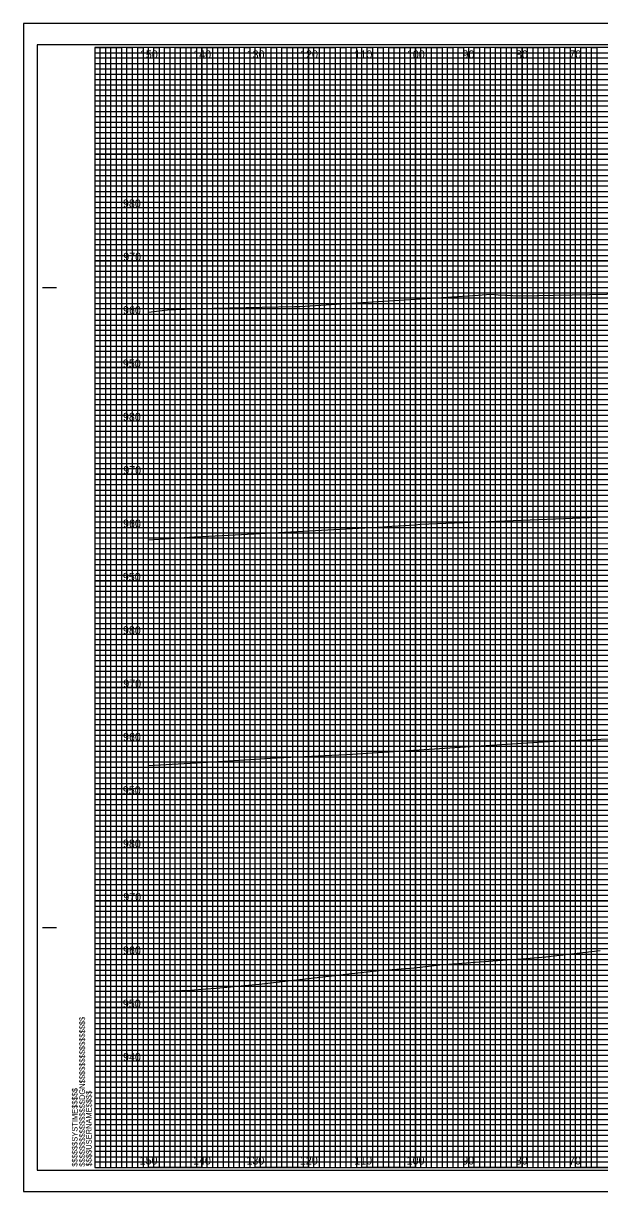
# Model space of a CAD drawing. Extents: x -13 to 760, y -5 to 1491.
# Drawn here: x -13.4 to 94.5, y 952.5 to 1171.5 of the extents above; entities that cross this region are included whole.
import ezdxf

# ---------------------------------------------------------------- set-up
doc = ezdxf.new("R2010")
doc.units = 0
for name, color, linetype in [('Default', 7, 'Continuous'), ('Exist XS Ground Line', 7, 'Continuous'), ('Prop XS Elevation Labels', 7, 'Continuous'), ('Prop XS Offset Labels', 7, 'Continuous'), ('Sheet Cross Section CELL', 7, 'Continuous'), ('Sheet Cross Section Grid Major CELL', 7, 'Continuous'), ('Sheet Cross Section Grid Middle CELL', 7, 'Continuous'), ('Sheet Cross Section Grid Minor 1 CELL', 7, 'Continuous'), ('Sheet Cross Section Grid Minor 2 CELL', 7, 'Continuous'), ('Sheet Cutting Line CELL', 7, 'Continuous'), ('Sheet DOT Grid CELL', 7, 'Continuous'), ('Sheet Plot Border Inside CELL', 7, 'Continuous'), ('Sheet Plot Border Outside CELL', 7, 'Continuous')]:
    doc.layers.add(name, color=color, linetype=linetype)

msp = doc.modelspace()

# ---------------------------------------------------------------- linework, layer by layer
at = {"layer": 'Exist XS Ground Line'}
for points in [[(10, 1117.39), (13.59, 1117.79), (16.76, 1117.93), (17.9, 1117.98), (19.18, 1118.04), (37.38, 1118.41), (38.34, 1118.46), (71.78, 1120.56), (74.07, 1120.73), (75.48, 1120.63), (79.56, 1120.43), (105.65, 1120.95)], [(10, 1117.39), (13.59, 1117.79), (16.76, 1117.93), (17.9, 1117.98), (19.18, 1118.04), (37.38, 1118.41), (38.34, 1118.46), (71.78, 1120.56), (74.07, 1120.73), (75.48, 1120.63), (79.56, 1120.43), (105.65, 1120.95)], [(10, 1074.69), (18.61, 1075.26), (25.12, 1075.57), (53.98, 1077.14), (55.61, 1077.26), (56.75, 1077.3), (59.91, 1077.53), (60.98, 1077.61), (102.01, 1079.28)], [(10, 1074.69), (18.61, 1075.26), (25.12, 1075.57), (53.98, 1077.14), (55.61, 1077.26), (56.75, 1077.3), (59.91, 1077.53), (60.98, 1077.61), (102.01, 1079.28)], [(10, 1032.38), (21.11, 1033.01), (32.79, 1033.79), (48.2, 1034.55), (67.4, 1035.78), (68.4, 1035.84), (84.99, 1036.87), (110.02, 1038.03)], [(10, 1032.38), (21.11, 1033.01), (32.79, 1033.79), (48.2, 1034.55), (67.4, 1035.78), (68.4, 1035.84), (84.99, 1036.87), (110.02, 1038.03)], [(10, 989.95), (12.76, 990.08), (17.94, 990.31), (20.77, 990.55), (22.71, 990.66), (30.73, 991.39), (48.12, 993.41), (52.64, 993.88), (53.2, 993.95), (59.79, 994.48), (64.6, 995), (67.1, 995.23), (74.49, 995.75), (80.75, 996.22), (84.4, 996.53), (85.41, 996.64), (94.63, 997.69)], [(10, 989.95), (12.76, 990.08), (17.94, 990.31), (20.77, 990.55), (22.71, 990.66), (30.73, 991.39), (48.12, 993.41), (52.64, 993.88), (53.2, 993.95), (59.79, 994.48), (64.6, 995), (67.1, 995.23), (74.49, 995.75), (80.75, 996.22), (84.4, 996.53), (85.41, 996.64), (94.63, 997.69)]]:
    msp.add_lwpolyline(points, dxfattribs=at)
at = {"layer": 'Sheet Cross Section CELL'}
for p, q in [((-9.8, 1122.01), (-7.3, 1122.01)), ((-9.7, 1122.01), (-7.2, 1122.01)), ((-9.8, 1002.01), (-7.3, 1002.01)), ((-9.7, 1002.01), (-7.2, 1002.01)), ((0, 957.01), (0, 957.01)), ((0, 957.01), (0, 957.01)), ((0, 957.01), (0, 957.01)), ((0, 957.01), (0, 957.01)), ((0, 957.01), (0, 957.01)), ((0, 957.01), (0, 957.01)), ((0, 957.01), (0, 957.01))]:
    msp.add_line(p, q, dxfattribs=at)
msp.add_lwpolyline([(320, 1167.01), (0, 1167.01), (0, 957.01), (320, 957.01)], close=True, dxfattribs=at)
at = {"layer": 'Sheet Cross Section Grid Major CELL'}
for p, q in [((10, 1167.01), (0, 1167.01)), ((10, 957.01), (10, 1167.01)), ((30, 1167.01), (20, 1167.01)), ((20, 1167.01), (20, 957.01)), ((30, 957.01), (30, 1167.01)), ((50, 1167.01), (40, 1167.01)), ((40, 1167.01), (40, 957.01)), ((50, 957.01), (50, 1167.01)), ((70, 1167.01), (60, 1167.01)), ((60, 1167.01), (60, 957.01)), ((70, 957.01), (70, 1167.01)), ((90, 1167.01), (80, 1167.01)), ((80, 1167.01), (80, 957.01)), ((90, 957.01), (90, 1167.01)), ((20, 957.01), (10, 957.01)), ((40, 957.01), (30, 957.01)), ((60, 957.01), (50, 957.01)), ((80, 957.01), (70, 957.01)), ((100, 957.01), (90, 957.01))]:
    msp.add_line(p, q, dxfattribs=at)
for points in [[(0, 1157.01), (320, 1157.01), (320, 1147.01), (0, 1147.01)], [(0, 1137.01), (320, 1137.01), (320, 1127.01), (0, 1127.01)], [(0, 1117.01), (320, 1117.01), (320, 1107.01), (0, 1107.01)], [(0, 1097.01), (320, 1097.01), (320, 1087.01), (0, 1087.01)], [(0, 1077.01), (320, 1077.01), (320, 1067.01), (0, 1067.01)], [(0, 1057.01), (320, 1057.01), (320, 1047.01), (0, 1047.01)], [(0, 1037.01), (320, 1037.01), (320, 1027.01), (0, 1027.01)], [(0, 1017.01), (320, 1017.01), (320, 1007.01), (0, 1007.01)], [(0, 997.01), (320, 997.01), (320, 987.01), (0, 987.01)], [(0, 977.01), (320, 977.01), (320, 967.01), (0, 967.01)]]:
    msp.add_lwpolyline(points, dxfattribs=at)
at = {"layer": 'Sheet Cross Section Grid Middle CELL'}
for points in [[(0, 1167.01), (5, 1167.01), (5, 957.01), (15, 957.01), (15, 1167.01), (25, 1167.01), (25, 957.01), (35, 957.01), (35, 1167.01), (45, 1167.01), (45, 957.01), (55, 957.01), (55, 1167.01), (65, 1167.01), (65, 957.01), (75, 957.01), (75, 1167.01), (85, 1167.01), (85, 957.01), (95, 957.01)], [(0, 1162.01), (275, 1162.01)], [(0, 1142.01), (320, 1142.01), (320, 1152.01), (0, 1152.01)], [(0, 1122.01), (320, 1122.01), (320, 1132.01), (0, 1132.01)], [(0, 1102.01), (320, 1102.01), (320, 1112.01), (0, 1112.01)], [(0, 1082.01), (320, 1082.01), (320, 1092.01), (0, 1092.01)], [(0, 1062.01), (320, 1062.01), (320, 1072.01), (0, 1072.01)], [(0, 1042.01), (320, 1042.01), (320, 1052.01), (0, 1052.01)], [(0, 1022.01), (320, 1022.01), (320, 1032.01), (0, 1032.01)], [(0, 1002.01), (320, 1002.01), (320, 1012.01), (0, 1012.01)], [(0, 982.01), (320, 982.01), (320, 992.01), (0, 992.01)], [(0, 962.01), (320, 962.01), (320, 972.01), (0, 972.01)]]:
    msp.add_lwpolyline(points, dxfattribs=at)
at = {"layer": 'Sheet Cross Section Grid Minor 1 CELL'}
for p, q in [((0, 1166.01), (260, 1166.01)), ((260, 1164.99), (0, 1164.99)), ((0, 1164.99), (0, 1164.01)), ((0, 1164.01), (260, 1164.01)), ((260, 1162.9), (0, 1162.9)), ((0, 1162.9), (0, 1161.01)), ((0, 1161.01), (320, 1161.01))]:
    msp.add_line(p, q, dxfattribs=at)
for points in [[(0, 1160.01), (270, 1160.01), (320, 1160.01), (320, 1159.01), (0, 1159.01)], [(0, 1158.01), (320, 1158.01), (320, 1156.01), (0, 1156.01)], [(0, 1155.01), (320, 1155.01), (320, 1154.01), (0, 1153.99)], [(0, 1153.01), (320, 1153.01), (320, 1151.01), (0, 1151.01)], [(0, 1150.01), (320, 1150.01), (320, 1149.01), (0, 1149.01)], [(0, 1148.01), (320, 1148.01), (320, 1146.01), (0, 1146.01)], [(0, 1145.01), (320, 1145.01), (320, 1144.01), (0, 1144.01)], [(0, 1143.01), (320, 1143.01), (320, 1141.01), (0, 1141.01)], [(0, 1140.01), (320, 1140.01), (320, 1139.01), (0, 1139.01)], [(0, 1138.01), (320, 1138.01), (320, 1136.01), (0, 1136.01)], [(0, 1135.01), (320, 1135.01), (320, 1134.01), (0, 1134.01)], [(0, 1133.01), (320, 1133.01), (320, 1130.96), (320, 1130.01), (320, 1129.01), (0, 1129.01)], [(0, 1131.01), (320, 1131.01), (320, 1130.01), (0, 1130.01)], [(0, 1128.01), (320, 1128.01), (320, 1126.01), (0, 1126.04)], [(0, 1126.04), (320, 1126.01), (320, 1125.01), (0, 1125.01)], [(0, 1124.01), (320, 1124.01), (320, 1123.01), (0, 1123.01)], [(0, 1121.01), (320, 1121.01), (320, 1120.01), (0, 1120.01)], [(0, 1119.01), (320, 1119.01), (320, 1118.01), (0, 1118.01)], [(-0.07, 1115.9), (320, 1115.9), (320, 1114.89), (-0.07, 1114.89)], [(0, 1114.01), (320, 1114.01), (320, 1113.01), (0, 1113.01)], [(0, 1111.01), (320, 1111.01), (320, 1110.01), (0, 1110.01)], [(0, 1109.01), (320, 1109.01), (320, 1108.01), (0, 1108.01)], [(0, 1106.01), (320, 1106.01), (320, 1105.01), (0, 1105.01)], [(0, 1104.01), (320, 1104.01), (320, 1103.01), (0, 1103.01)], [(0, 1101.01), (320, 1101.01), (320, 1100.01), (0, 1100.01)], [(0, 1099.01), (320, 1099.01), (320, 1098.01), (0, 1098.01)], [(0, 1096.01), (320, 1096.01), (319.99, 1094.99), (0, 1095.01)], [(0, 1094.01), (320, 1094.01), (320, 1093.01), (0, 1093.01)], [(0, 1091.01), (320, 1091.01), (320, 1090.01), (0, 1090.01)], [(0, 1089.01), (320, 1089.01), (320, 1088.01), (0, 1088.01)], [(0, 1086.01), (320, 1086.01), (320, 1085.01), (0, 1085.01)], [(0, 1084.01), (320, 1084.01), (320, 1083.01), (0, 1083.01)], [(0, 1081.01), (320, 1081.01), (320, 1080.01), (0, 1080.01)], [(0, 1079.01), (320, 1079.01), (320, 1078.01), (0, 1078.01)], [(0, 1076.01), (320, 1076.01), (320, 1075.01), (0, 1075.01)], [(0, 1074), (320.07, 1073.92), (320, 1073.01), (0, 1073.01)], [(0, 1071.01), (320, 1071.01), (320, 1070.01), (0, 1070.01)], [(0, 1069.01), (320, 1069.01), (320, 1068.01), (0, 1068.01)], [(0, 1066.01), (320, 1066.01), (320, 1065.01), (0, 1065.01)], [(0, 1064.01), (320, 1064.01), (320, 1063.01), (0, 1063.01)], [(0, 1061.01), (320, 1061.01), (320, 1060.01), (0, 1060.01)], [(0, 1059.01), (320, 1059.01), (320, 1058.01), (0, 1058.01)], [(0, 1056.01), (320, 1056.01), (320, 1055.01), (0, 1055.01)], [(0, 1054.01), (320, 1054.01), (320, 1053.01), (0, 1053.01)], [(0, 1051.01), (320, 1051.01), (320, 1050.01), (0, 1050.01)], [(0, 1049.01), (320, 1049.01), (320, 1048.01), (0, 1048.01)], [(0, 1046.01), (320, 1046.01), (320, 1045.01), (0, 1045.01)], [(0, 1044.01), (320, 1044.01), (320, 1043.01), (0, 1043.01)], [(0, 1041.01), (320, 1041.01), (320, 1040.01), (0, 1040.01)], [(0, 1039.01), (320, 1039.01), (320, 1038.01), (0, 1038.01)], [(0, 1036.01), (320, 1036.01), (319.99, 1034.99), (0, 1035.01)], [(0, 1034.01), (320, 1034.01), (320, 1033.01), (0, 1033.01)], [(0, 1031.01), (320, 1031.01), (320, 1030.01), (0, 1030.01)], [(0, 1029.01), (320, 1029.01), (320, 1028.01), (0, 1028.01)], [(0, 1026.01), (320, 1026.01), (320, 1025.01), (0, 1025.01)], [(0, 1024.01), (320, 1024.01), (320, 1023.01), (0, 1023.01)], [(0, 1021.01), (320, 1021.01), (320, 1020.01), (0, 1020.01)], [(0, 1019.01), (320, 1019.01), (320, 1018.01), (0, 1018.01)], [(0, 1016.01), (320, 1016.01), (320, 1015.01), (0, 1015.01)], [(0, 1014), (320.07, 1013.92), (320, 1013.01), (0, 1013.01)], [(0, 1011.01), (320, 1011.01), (320, 1010.01), (0, 1010.01)], [(0, 1009.01), (320, 1009.01), (320, 1008.01), (0, 1008.01)], [(0, 1006.01), (320, 1006.01), (320, 1005.01), (0, 1005.01)], [(0, 1004.01), (320, 1004.01), (320, 1003.01), (0, 1003.01)], [(0, 1001.01), (320, 1001.01), (320, 1000.01), (0, 1000.01)], [(0, 999.01), (320, 999.01), (320, 998.01), (0, 998.01)], [(0, 996.01), (320, 996.01), (320, 995.01), (0, 995.01)], [(0, 994.01), (320, 994.01), (320, 993.01), (0, 993.01)], [(0, 991.01), (320, 991.01), (320, 990.01), (0, 990.01)], [(0, 989.01), (320, 989.01), (320, 988.01), (0, 988.01)], [(0, 986.01), (320, 986.01), (320, 985.01), (0, 985.01)], [(0, 984.01), (320, 984.01), (320, 983.01), (0, 983.01)], [(0, 981.01), (320, 981.01), (320, 980.01), (0, 980.01)], [(0, 979.01), (320, 979.01), (320, 978.01), (0, 978.01)], [(0, 976.01), (320, 976.01), (320, 975.01), (0, 975.01)], [(0, 974.01), (320, 974.01), (320, 973.01), (0, 973.01)], [(0, 971.01), (320, 971.01), (320, 970.01), (0, 970.01)], [(0, 969.01), (320, 969.01), (320, 968.01), (0, 968.01)], [(0, 966.01), (320, 966.01), (320, 965.01), (0, 965.01)], [(0, 964.01), (320, 964.01), (320, 963.01), (0, 963.01)], [(0, 961.01), (320, 961.01), (320, 960.01), (0, 960.01)], [(0, 959.01), (320, 959.01), (320, 958.01), (0, 958.01)]]:
    msp.add_lwpolyline(points, dxfattribs=at)
at = {"layer": 'Sheet Cross Section Grid Minor 2 CELL'}
for points in [[(0, 957.01), (1, 957.01), (1, 1167.01), (2, 1167.01), (2, 957.01)], [(2, 957.01), (3, 957.01), (3, 1167.01), (4, 1167.01), (4, 957.01)], [(5, 957.01), (6, 957.01), (6, 1167.01), (7, 1167.01), (7, 957.01)], [(7, 957.01), (8, 957.01), (8, 1167.01), (9, 1167.01), (9, 957.01)], [(10, 957.01), (11, 957.01), (11, 1167.01), (12, 1167.01), (12, 957.01)], [(12, 957.01), (13, 957.01), (13, 1167.01), (14, 1167.01), (14, 957.01)], [(15, 957.01), (16, 957.01), (16, 1167.01), (17, 1167.01), (17, 957.01)], [(17, 957.01), (18, 957.01), (18, 1167.01), (19, 1167.01), (19, 957.01)], [(20, 957.01), (21, 957.01), (21, 1167.01), (22, 1167.01), (22, 957.01)], [(22, 957.01), (23, 957.01), (23, 1167.01), (24, 1167.01), (24, 957.01)], [(25, 957.01), (26, 957.01), (26, 1167.01), (27, 1167.01), (27, 957.01)], [(27, 957.01), (28, 957.01), (28, 1167.01), (29, 1167.01), (29, 957.01)], [(30, 957.01), (31, 957.01), (31, 1167.01), (32, 1167.01), (32, 957.01)], [(32, 957.01), (33, 957.01), (33, 1167.01), (34, 1167.01), (34, 957.01)], [(35, 957.01), (36, 957.01), (36, 1167.01), (37, 1167.01), (37, 957.01)], [(37, 957.01), (38, 957.01), (38, 1167.01), (39, 1167.01), (39, 957.01)], [(40, 957.01), (41, 957.01), (41, 1167.01), (42, 1167.01), (42, 957.01)], [(42, 957.01), (43, 957.01), (43, 1167.01), (44, 1167.01), (44, 957.01)], [(45, 957.01), (46, 957.01), (46, 1167.01), (47, 1167.01), (47, 957.01)], [(47, 957.01), (48, 957.01), (48, 1167.01), (49, 1167.01), (49, 957.01)], [(50, 957.01), (51, 957.01), (51, 1167.01), (52, 1167.01), (52, 957.01)], [(52, 957.01), (53, 957.01), (53, 1167.01), (54, 1167.01), (54, 957.01)], [(55, 957.01), (56, 957.01), (56, 1167.01), (57, 1167.01), (57, 957.01)], [(57, 957.01), (58, 957.01), (58, 1167.01), (59, 1167.01), (59, 957.01)], [(60, 957.01), (61, 957.01), (61, 1167.01), (62, 1167.01), (62, 957.01)], [(62, 957.01), (63, 957.01), (63, 1167.01), (64, 1167.01), (64, 957.01)], [(65, 957.01), (66, 957.01), (66, 1167.01), (67, 1167.01), (67, 957.01)], [(67, 957.01), (68, 957.01), (68, 1167.01), (69, 1167.01), (69, 957.01)], [(70, 957.01), (71, 957.01), (71, 1167.01), (72, 1167.01), (72, 957.01)], [(72, 957.01), (73, 957.01), (73, 1167.01), (74, 1167.01), (74, 957.01)], [(75, 957.01), (76, 957.01), (76, 1167.01), (77, 1167.01), (77, 957.01)], [(77, 957.01), (78, 957.01), (78, 1167.01), (79, 1167.01), (79, 957.01)], [(80, 957.01), (81, 957.01), (81, 1167.01), (82, 1167.01), (82, 957.01)], [(82, 957.01), (83, 957.01), (83, 1167.01), (84, 1167.01), (84, 957.01)], [(85, 957.01), (86, 957.01), (86, 1167.01), (87, 1167.01), (87, 957.01)], [(87, 957.01), (88, 957.01), (88, 1167.01), (89, 1167.01), (89, 957.01)], [(90, 957.01), (91, 957.01), (91, 1167.01), (92, 1167.01), (92, 957.01)], [(92, 957.01), (93, 957.01), (93, 1167.01), (94, 1167.01), (94, 957.01)]]:
    msp.add_lwpolyline(points, dxfattribs=at)
at = {"layer": 'Sheet Cutting Line CELL'}
for p, q in [((323.3, 1171.51), (-13.4, 1171.51)), ((-13.4, 1171.51), (-13.4, 952.51)), ((-13.4, 952.51), (323.3, 952.51))]:
    msp.add_line(p, q, dxfattribs=at)
at = {"layer": 'Sheet DOT Grid CELL'}
for p, q in [((10, 957.01), (10, 1167.01)), ((20, 957.01), (20, 1167.01)), ((30, 957.01), (30, 1167.01)), ((40, 957.01), (40, 1167.01)), ((50, 957.01), (50, 1167.01)), ((60, 957.01), (60, 1167.01)), ((70, 957.01), (70, 1167.01)), ((80, 957.01), (80, 1167.01)), ((90, 957.01), (90, 1167.01)), ((0, 1157.01), (320, 1157.01)), ((0, 1147.01), (320, 1147.01)), ((0, 1137.01), (320, 1137.01)), ((0, 1127.01), (320, 1127.01)), ((0, 1117.01), (320, 1117.01)), ((0, 1107.01), (320, 1107.01)), ((0, 1097.01), (320, 1097.01)), ((0, 1087.01), (320, 1087.01)), ((0, 1077.01), (320, 1077.01)), ((0, 1067.01), (320, 1067.01)), ((0, 1057.01), (320, 1057.01)), ((0, 1047.01), (320, 1047.01)), ((0, 1037.01), (320, 1037.01)), ((0, 1027.01), (320, 1027.01)), ((0, 1017.01), (320, 1017.01)), ((0, 1007.01), (320, 1007.01)), ((0, 997.01), (320, 997.01)), ((0, 987.01), (320, 987.01)), ((0, 977.01), (320, 977.01)), ((0, 967.01), (320, 967.01))]:
    msp.add_line(p, q, dxfattribs=at)
at = {"layer": 'Sheet Plot Border Inside CELL'}
msp.add_lwpolyline([(-10.8, 956.51), (322.4, 956.51), (322.4, 1167.51), (-10.8, 1167.51)], close=True, dxfattribs=at)
at = {"layer": 'Sheet Plot Border Outside CELL'}
msp.add_lwpolyline([(-13.4, 952.51), (323.3, 952.51), (323.3, 1171.51), (-13.4, 1171.51)], close=True, dxfattribs=at)

# ---------------------------------------------------------------- texts
at = {"layer": 'Default'}
for p in [(10, 1107.01), (10, 1067.01), (10, 1027.01), (10, 977.01)]:
    msp.add_text('-', height=0.0001, dxfattribs=at).set_placement(p)
at = {"layer": 'Prop XS Elevation Labels'}
for s, p in [('980', (5.24, 1137.01)), ('970', (5.3, 1127.01)), ('960', (5.26, 1117.01)), ('950', (5.22, 1107.01)), ('980', (5.24, 1097.01)), ('970', (5.3, 1087.01)), ('960', (5.26, 1077.01)), ('950', (5.22, 1067.01)), ('980', (5.24, 1057.01)), ('970', (5.3, 1047.01)), ('960', (5.26, 1037.01)), ('950', (5.22, 1027.01)), ('980', (5.24, 1017.01)), ('970', (5.3, 1007.01)), ('960', (5.26, 997.01)), ('950', (5.22, 987.01)), ('940', (5.26, 977.01))]:
    msp.add_text(s, height=1.5, dxfattribs=at).set_placement(p)
at = {"layer": 'Prop XS Offset Labels'}
for s, p in [('150', (8.41, 1164.95)), ('140', (18.41, 1164.95)), ('130', (28.41, 1164.95)), ('120', (38.41, 1164.95)), ('110', (48.59, 1164.95)), ('100', (58.41, 1164.95)), ('90', (68.83, 1164.95)), ('80', (78.83, 1164.95)), ('70', (88.83, 1164.95)), ('150', (8.37, 957.6)), ('140', (18.37, 957.6)), ('130', (28.37, 957.6)), ('120', (38.37, 957.6)), ('110', (48.55, 957.6)), ('100', (58.37, 957.6)), ('90', (68.78, 957.6)), ('80', (78.78, 957.6)), ('70', (88.78, 957.6))]:
    msp.add_text(s, height=1.5, dxfattribs=at).set_placement(p)
at = {"layer": 'Sheet Cross Section CELL'}
for s, p in [('$$$$$$$$$$$$$$$$DGN$$$$$$$$$$$$$$$$', (-1.88, 957.19)), ('$$$$$$SYSTIME$$$$$', (-3.26, 957.19)), ('$$$$USERNAME$$$$', (-0.62, 957.24))]:
    msp.add_text(s, height=1.05, rotation=90, dxfattribs=at).set_placement(p)

doc.saveas('drawing.dxf')
